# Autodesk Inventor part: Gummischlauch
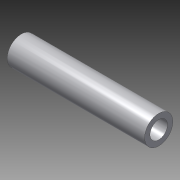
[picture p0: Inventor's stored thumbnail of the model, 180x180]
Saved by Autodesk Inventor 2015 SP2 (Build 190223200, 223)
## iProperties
Created: 2012-07
Part Number: Gummischlauch
Material: PVC, hart
Document SubType Name: Modeling
Designer: rYan
Mass: 5.1874 g
Surface Area: 41.469 cm^2
Volume: 4.02124 cm^3
Density: 1.29 g/cm^3
Appearance: Glatt - weiß
Author: rYan
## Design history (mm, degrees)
sketch "Skizze1"
  geometry: C1 r 5 at (0, 0); C2 r 8 at (0, 0); 1 further point
  constraints: 2 centre point, 2 coincident
  dimensions: "d0" = 10 diameter of C1; "d4" = 16 diameter of C2
extrude "Extrusion1" new body sketch "Skizze1" distance "d2" = 78; taper "d3" = 0 deg
node "Volumenkörper1"
